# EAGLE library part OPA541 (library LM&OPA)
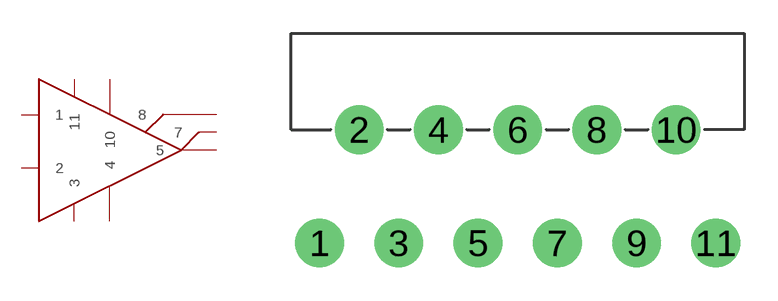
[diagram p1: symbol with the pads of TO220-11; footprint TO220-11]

Designator prefix -

## OPA541  [TO220-11]
1  1  in
2  2  in
3  3  pwr
4  4  pwr
5  5  out
7  7  out
8  8
10  10  pwr
11  11  pwr

## Footprint TO220-11 (pad centres in mm)
drill 1.016 pad 2.184 round: 1 -8.89,-2.54; 2 -7.112,2.54; 3 -5.334,-2.54; 4 -3.556,2.54; 5 -1.778,-2.54; 6 0,2.54; 7 1.778,-2.54; 8 3.556,2.54; 9 5.334,-2.54; 10 7.112,2.54; 11 8.89,-2.54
